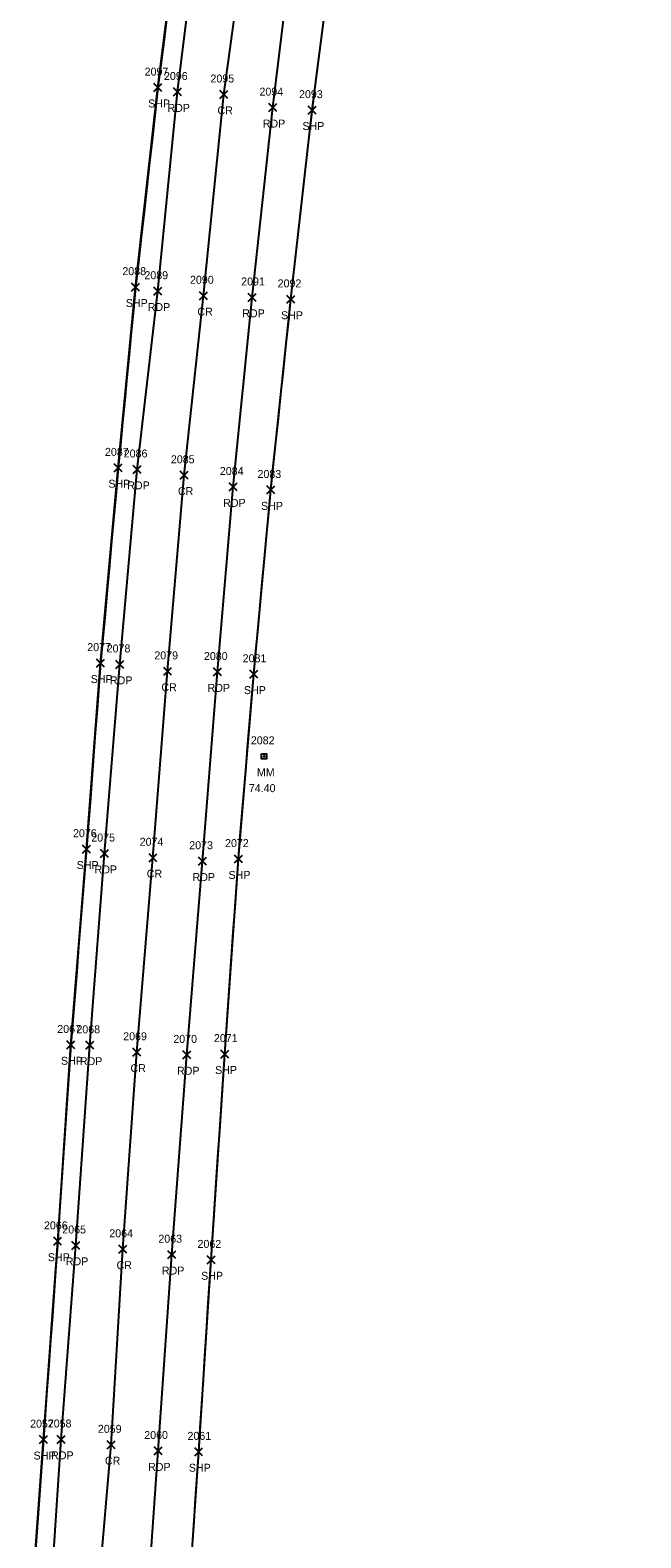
# Model space of a CAD drawing. Extents: x 1688195 to 1692013, y 424605 to 441234.
# Drawn here: x 1690667.5 to 1690820.9, y 437155.9 to 437534.4 of the extents above; entities that cross this region are included whole.
import ezdxf

# ---------------------------------------------------------------- set-up
doc = ezdxf.new("R2010")
doc.units = 0
for name, color, linetype in [('LSOGP', 7, 'Continuous'), ('P_A', 7, 'Continuous'), ('P_I', 7, 'Continuous'), ('P_TIC', 7, 'Continuous'), ('PET', 7, 'Continuous'), ('PRC', 7, 'Continuous'), ('PSP', 7, 'Continuous'), ('S_A', 7, 'Continuous'), ('S_C', 7, 'Continuous'), ('S_I', 7, 'Continuous'), ('SRM', 7, 'Continuous')]:
    doc.layers.add(name, color=color, linetype=linetype)

msp = doc.modelspace()

# ---------------------------------------------------------------- linework, layer by layer
at = {"layer": 'LSOGP'}
for points in [[(1690701.79, 437537.1), (1690701.08, 437531.4), (1690700.36, 437525.71), (1690699.64, 437520.01), (1690698.94, 437513.75), (1690698.24, 437507.48), (1690697.54, 437501.22), (1690696.84, 437494.96), (1690696.14, 437488.7), (1690695.44, 437482.43), (1690694.74, 437476.17), (1690694.03, 437469.91), (1690693.49, 437464.24), (1690692.94, 437458.57), (1690692.4, 437452.9), (1690691.85, 437447.23), (1690691.3, 437441.56), (1690690.76, 437435.89), (1690690.21, 437430.21), (1690689.67, 437424.54), (1690689.11, 437418.41), (1690688.56, 437412.29), (1690688, 437406.16), (1690687.45, 437400.03), (1690686.89, 437393.9), (1690686.34, 437387.77), (1690685.79, 437381.64), (1690685.23, 437375.51), (1690684.79, 437369.67), (1690684.35, 437363.83), (1690683.91, 437357.99), (1690683.46, 437352.15), (1690683.02, 437346.31), (1690682.58, 437340.48), (1690681.2, 437322.65), (1690680.71, 437316.51), (1690680.22, 437310.37), (1690679.72, 437304.23), (1690679.23, 437298.08), (1690678.73, 437291.94), (1690678.24, 437285.8), (1690677.75, 437279.66), (1690677.34, 437273.49), (1690676.93, 437267.33), (1690676.52, 437261.16), (1690676.1, 437255), (1690675.69, 437248.83), (1690675.28, 437242.67), (1690674.87, 437236.5), (1690674.46, 437230.34), (1690674.01, 437224.11), (1690673.57, 437217.89), (1690673.12, 437211.66), (1690672.67, 437205.44), (1690672.22, 437199.21), (1690671.77, 437192.99), (1690671.32, 437186.77), (1690670.88, 437180.54), (1690670.46, 437174.76), (1690670.04, 437168.98), (1690669.63, 437163.19), (1690669.21, 437157.41), (1690668.8, 437151.63)], [(1690708.3, 437154.13), (1690708.69, 437159.97), (1690709.08, 437165.8), (1690709.47, 437171.64), (1690709.86, 437177.48), (1690710.25, 437183.51), (1690710.64, 437189.53), (1690711.03, 437195.56), (1690711.41, 437201.58), (1690711.8, 437207.61), (1690712.19, 437213.63), (1690712.57, 437219.66), (1690712.96, 437225.68), (1690713.4, 437232.14), (1690713.83, 437238.6), (1690714.27, 437245.06), (1690714.7, 437251.52), (1690715.14, 437257.97), (1690715.58, 437264.43), (1690716.01, 437270.89), (1690716.45, 437277.35), (1690716.87, 437283.47), (1690717.29, 437289.59), (1690717.71, 437295.71), (1690718.14, 437301.84), (1690718.56, 437307.96), (1690718.98, 437314.08), (1690719.4, 437320.2), (1690719.82, 437326.32), (1690720.31, 437332.12), (1690720.79, 437337.92), (1690721.27, 437343.72), (1690721.76, 437349.52), (1690722.24, 437355.32), (1690722.72, 437361.12), (1690723.2, 437366.92), (1690723.69, 437372.72), (1690724.22, 437378.5), (1690724.76, 437384.28), (1690725.29, 437390.07), (1690725.83, 437395.85), (1690726.37, 437401.63), (1690726.9, 437407.41), (1690727.44, 437413.2), (1690727.97, 437418.98), (1690728.6, 437424.96), (1690729.23, 437430.95), (1690729.87, 437436.93), (1690730.5, 437442.91), (1690731.13, 437448.89), (1690731.76, 437454.87), (1690732.39, 437460.86), (1690733.02, 437466.84), (1690733.69, 437472.78), (1690734.36, 437478.72), (1690735.03, 437484.65), (1690735.7, 437490.59), (1690736.37, 437496.53), (1690737.04, 437502.47), (1690737.71, 437508.41), (1690739.13, 437520.19), (1690739.89, 437526.02), (1690740.64, 437531.86), (1690741.39, 437537.7)]]:
    msp.add_lwpolyline(points, dxfattribs=at)
at = {"layer": 'P_TIC'}
for points in [[(1690698.64, 437519.01), (1690700.64, 437521.01)], [(1690700.64, 437519.01), (1690698.64, 437521.01)], [(1690703.53, 437517.9), (1690705.53, 437519.9)], [(1690705.53, 437517.9), (1690703.53, 437519.9)], [(1690715.15, 437517.28), (1690717.15, 437519.28)], [(1690717.15, 437517.28), (1690715.15, 437519.28)], [(1690727.46, 437513.97), (1690729.46, 437515.97)], [(1690729.46, 437513.97), (1690727.46, 437515.97)], [(1690737.38, 437513.35), (1690739.38, 437515.35)], [(1690739.38, 437513.35), (1690737.38, 437515.35)], [(1690693.03, 437468.91), (1690695.03, 437470.91)], [(1690695.03, 437468.91), (1690693.03, 437470.91)], [(1690698.57, 437467.9), (1690700.57, 437469.9)], [(1690700.57, 437467.9), (1690698.57, 437469.9)], [(1690710.1, 437466.75), (1690712.1, 437468.75)], [(1690712.1, 437466.75), (1690710.1, 437468.75)], [(1690722.31, 437466.32), (1690724.31, 437468.32)], [(1690724.31, 437466.32), (1690722.31, 437468.32)], [(1690732.02, 437465.84), (1690734.02, 437467.84)], [(1690734.02, 437465.84), (1690732.02, 437467.84)], [(1690688.67, 437423.54), (1690690.67, 437425.54)], [(1690690.67, 437423.54), (1690688.67, 437425.54)], [(1690693.44, 437423.13), (1690695.44, 437425.13)], [(1690695.44, 437423.13), (1690693.44, 437425.13)], [(1690705.22, 437421.68), (1690707.22, 437423.68)], [(1690707.22, 437421.68), (1690705.22, 437423.68)], [(1690717.51, 437418.73), (1690719.51, 437420.73)], [(1690719.51, 437418.73), (1690717.51, 437420.73)], [(1690726.97, 437417.98), (1690728.97, 437419.98)], [(1690728.97, 437417.98), (1690726.97, 437419.98)], [(1690684.23, 437374.51), (1690686.23, 437376.51)], [(1690686.23, 437374.51), (1690684.23, 437376.51)], [(1690689.1, 437374.18), (1690691.1, 437376.18)], [(1690691.1, 437374.18), (1690689.1, 437376.18)], [(1690701.07, 437372.44), (1690703.07, 437374.44)], [(1690703.07, 437372.44), (1690701.07, 437374.44)], [(1690713.61, 437372.28), (1690715.61, 437374.28)], [(1690715.61, 437372.28), (1690713.61, 437374.28)], [(1690722.69, 437371.72), (1690724.69, 437373.72)], [(1690724.69, 437371.72), (1690722.69, 437373.72)], [(1690680.7, 437327.8), (1690682.7, 437329.8)], [(1690682.7, 437327.8), (1690680.7, 437329.8)], [(1690685.24, 437326.7), (1690687.24, 437328.7)], [(1690687.24, 437326.7), (1690685.24, 437328.7)], [(1690697.39, 437325.64), (1690699.39, 437327.64)], [(1690699.39, 437325.64), (1690697.39, 437327.64)], [(1690709.83, 437324.78), (1690711.83, 437326.78)], [(1690711.83, 437324.78), (1690709.83, 437326.78)], [(1690718.82, 437325.32), (1690720.82, 437327.32)], [(1690720.82, 437325.32), (1690718.82, 437327.32)], [(1690676.75, 437278.66), (1690678.75, 437280.66)], [(1690678.75, 437278.66), (1690676.75, 437280.66)], [(1690681.55, 437278.56), (1690683.55, 437280.56)], [(1690683.55, 437278.56), (1690681.55, 437280.56)], [(1690693.3, 437276.81), (1690695.3, 437278.81)], [(1690695.3, 437276.81), (1690693.3, 437278.81)], [(1690705.92, 437276.15), (1690707.92, 437278.15)], [(1690707.92, 437276.15), (1690705.92, 437278.15)], [(1690715.45, 437276.35), (1690717.45, 437278.35)], [(1690717.45, 437276.35), (1690715.45, 437278.35)], [(1690673.46, 437229.34), (1690675.46, 437231.34)], [(1690675.46, 437229.34), (1690673.46, 437231.34)], [(1690678.01, 437228.3), (1690680.01, 437230.3)], [(1690680.01, 437228.3), (1690678.01, 437230.3)], [(1690689.8, 437227.34), (1690691.8, 437229.34)], [(1690691.8, 437227.34), (1690689.8, 437229.34)], [(1690702.13, 437225.98), (1690704.13, 437227.98)], [(1690704.13, 437225.98), (1690702.13, 437227.98)], [(1690711.96, 437224.68), (1690713.96, 437226.68)], [(1690713.96, 437224.68), (1690711.96, 437226.68)], [(1690669.88, 437179.54), (1690671.88, 437181.54)], [(1690671.88, 437179.54), (1690669.88, 437181.54)], [(1690674.32, 437179.59), (1690676.32, 437181.59)], [(1690676.32, 437179.59), (1690674.32, 437181.59)], [(1690686.9, 437178.25), (1690688.9, 437180.25)], [(1690688.9, 437178.25), (1690686.9, 437180.25)], [(1690698.66, 437176.7), (1690700.66, 437178.7)], [(1690700.66, 437176.7), (1690698.66, 437178.7)], [(1690708.86, 437176.48), (1690710.86, 437178.48)], [(1690710.86, 437176.48), (1690708.86, 437178.48)]]:
    msp.add_lwpolyline(points, dxfattribs=at)
at = {"layer": 'PET'}
for points in [[(1690672.22, 437133.51), (1690675.32, 437180.59), (1690679.01, 437229.3), (1690682.55, 437279.56), (1690686.24, 437327.7), (1690690.1, 437375.18), (1690694.44, 437424.13), (1690699.57, 437468.9), (1690704.53, 437518.9), (1690710.13, 437564.01), (1690717.45, 437613.51), (1690724.9, 437659.11), (1690733.64, 437706.61), (1690742.78, 437751.42), (1690753.16, 437799.33), (1690763.08, 437842.79), (1690775.14, 437892.19), (1690786.57, 437936.04)], [(1690696.48, 437132.39), (1690699.66, 437177.7), (1690703.13, 437226.98), (1690706.92, 437277.15), (1690710.83, 437325.78), (1690714.61, 437373.28), (1690718.51, 437419.73), (1690723.31, 437467.32), (1690728.46, 437514.97), (1690734.16, 437561.66), (1690741.31, 437609.81), (1690748.91, 437655.66), (1690757.6, 437701.13), (1690766.63, 437747.05), (1690776.69, 437793.46), (1690786.88, 437837.7), (1690799.47, 437885.38), (1690811.72, 437928.04)]]:
    msp.add_lwpolyline(points, dxfattribs=at)
at = {"layer": 'PRC'}
msp.add_lwpolyline([(1690683.84, 437132.47), (1690687.9, 437179.25), (1690690.8, 437228.34), (1690694.3, 437277.81), (1690698.39, 437326.64), (1690702.07, 437373.44), (1690706.22, 437422.68), (1690711.1, 437467.75), (1690716.15, 437518.28), (1690722.22, 437562.2), (1690730.06, 437611.38), (1690736.55, 437656.66), (1690745.44, 437704.08), (1690754.49, 437748.99), (1690764.83, 437796.93), (1690774.84, 437839.91), (1690787.43, 437889.13), (1690798.27, 437931.55)], dxfattribs=at)
at = {"layer": 'PSP'}
for points in [[(1690667.55, 437134.28), (1690670.88, 437180.54), (1690674.46, 437230.34), (1690677.75, 437279.66), (1690681.7, 437328.8), (1690685.23, 437375.51), (1690689.67, 437424.54), (1690694.03, 437469.91), (1690699.64, 437520.01), (1690705.37, 437565.59), (1690712.95, 437613.82), (1690720.29, 437660.12), (1690729.03, 437707.25), (1690738.2, 437752.28), (1690748.49, 437800.46), (1690758.48, 437844.3), (1690771.1, 437893.4), (1690782.23, 437936.63)], [(1690706.73, 437130.77), (1690709.86, 437177.48), (1690712.96, 437225.68), (1690716.45, 437277.35), (1690719.82, 437326.32), (1690723.69, 437372.72), (1690727.97, 437418.98), (1690733.02, 437466.84), (1690738.38, 437514.35), (1690744.39, 437561.06), (1690751.89, 437609.7), (1690759.58, 437654.53), (1690768.24, 437698.48), (1690777.05, 437745.54), (1690787.15, 437791.22), (1690797.5, 437836.1), (1690809.46, 437882.47), (1690820.87, 437925.64)]]:
    msp.add_lwpolyline(points, dxfattribs=at)
at = {"layer": 'SRM'}
msp.add_lwpolyline([(1690725.67, 437352.74), (1690726.92, 437352.74), (1690726.92, 437351.49), (1690725.67, 437351.49)], close=True, dxfattribs=at)
msp.add_circle((1690726.29, 437352.11), 0.0833, dxfattribs=at)

# ---------------------------------------------------------------- texts
at = {"layer": 'P_A'}
for s, p in [('SHP', (1690697.18, 437515.01)), ('RDP', (1690702.02, 437513.9)), ('CR', (1690714.59, 437513.28)), ('RDP', (1690725.94, 437509.97)), ('SHP', (1690735.92, 437509.35)), ('SHP', (1690691.57, 437464.91)), ('RDP', (1690697.06, 437463.9)), ('CR', (1690709.54, 437462.75)), ('RDP', (1690720.8, 437462.32)), ('SHP', (1690730.55, 437461.84)), ('SHP', (1690687.2, 437419.54)), ('RDP', (1690691.93, 437419.13)), ('CR', (1690704.65, 437417.68)), ('RDP', (1690716, 437414.73)), ('SHP', (1690725.51, 437413.98)), ('SHP', (1690682.77, 437370.51)), ('RDP', (1690687.58, 437370.18)), ('CR', (1690700.5, 437368.44)), ('RDP', (1690712.09, 437368.28)), ('SHP', (1690721.22, 437367.72)), ('SHP', (1690679.23, 437323.8)), ('RDP', (1690683.72, 437322.7)), ('CR', (1690696.82, 437321.64)), ('RDP', (1690708.32, 437320.78)), ('SHP', (1690717.36, 437321.32)), ('SHP', (1690675.28, 437274.66)), ('RDP', (1690680.03, 437274.56)), ('CR', (1690692.74, 437272.81)), ('RDP', (1690704.41, 437272.15)), ('SHP', (1690713.98, 437272.35)), ('SHP', (1690672, 437225.34)), ('RDP', (1690676.5, 437224.3)), ('CR', (1690689.24, 437223.34)), ('RDP', (1690700.62, 437221.98)), ('SHP', (1690710.49, 437220.68)), ('SHP', (1690668.41, 437175.54)), ('RDP', (1690672.81, 437175.59)), ('CR', (1690686.33, 437174.25)), ('RDP', (1690697.15, 437172.7)), ('SHP', (1690707.4, 437172.48))]:
    msp.add_text(s, height=2, dxfattribs=at).set_placement(p)
at = {"layer": 'P_I'}
for s, p in [('2097', (1690696.3, 437523.01)), ('2096', (1690701.14, 437521.9)), ('2095', (1690712.82, 437521.28)), ('2094', (1690725.12, 437517.97)), ('2093', (1690735.05, 437517.35)), ('2088', (1690690.7, 437472.91)), ('2089', (1690696.23, 437471.9)), ('2090', (1690707.68, 437470.75)), ('2091', (1690720.54, 437470.32)), ('2092', (1690729.68, 437469.84)), ('2087', (1690686.33, 437427.54)), ('2086', (1690691.04, 437427.13)), ('2085', (1690702.88, 437425.68)), ('2084', (1690715.17, 437422.73)), ('2083', (1690724.63, 437421.98)), ('2077', (1690681.89, 437378.51)), ('2078', (1690686.76, 437378.18)), ('2079', (1690698.73, 437376.44)), ('2080', (1690711.18, 437376.28)), ('2081', (1690720.91, 437375.72)), ('2076', (1690678.3, 437331.8)), ('2075', (1690682.9, 437330.7)), ('2074', (1690695.05, 437329.64)), ('2073', (1690707.49, 437328.78)), ('2072', (1690716.49, 437329.32)), ('2067', (1690674.36, 437282.66)), ('2068', (1690679.16, 437282.56)), ('2069', (1690690.91, 437280.81)), ('2070', (1690703.49, 437280.15)), ('2071', (1690713.68, 437280.35)), ('2066', (1690671.02, 437233.34)), ('2065', (1690675.62, 437232.3)), ('2064', (1690687.42, 437231.34)), ('2063', (1690699.74, 437229.98)), ('2062', (1690709.57, 437228.68)), ('2057', (1690667.54, 437183.54)), ('2058', (1690671.98, 437183.59)), ('2059', (1690684.55, 437182.25)), ('2060', (1690696.19, 437180.7)), ('2061', (1690707.05, 437180.48))]:
    msp.add_text(s, height=2, dxfattribs=at).set_placement(p)
at = {"layer": 'S_A'}
msp.add_text('MM', height=2, dxfattribs=at).set_placement((1690724.48, 437347.11))
at = {"layer": 'S_C'}
msp.add_text('74.40', height=2, dxfattribs=at).set_placement((1690722.46, 437343.11))
at = {"layer": 'S_I'}
msp.add_text('2082', height=2, dxfattribs=at).set_placement((1690722.96, 437355.11))

doc.saveas('drawing.dxf')
